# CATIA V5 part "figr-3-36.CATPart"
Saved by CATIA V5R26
Part number: Part1
Bounding box of the stored display mesh (mm): x 0 to 71.72, y -62.404 to 71.526, z 0 to 0
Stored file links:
  D:\_Deepak\CATIA\CATIA V5 2015 Parts Files\Part files\Partfiles\c03_catia_v5_6r2015_prt\figr-3-36.CATPart
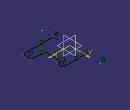
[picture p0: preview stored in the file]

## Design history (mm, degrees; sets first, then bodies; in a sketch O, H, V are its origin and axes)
Body1 (main body)
  Sketch1 on xy-plane, origin (0, 0, 0), H (1, 0, 0), V (0, 1, 0)
    axis line L1 (0, 71.5261) -> (1.8602, -62.4039)
    point P1 (0, 71.5261)
    line L2 (0.4896, 36.2738) -> (51.465, 36.2738)
    point P3 (0.4896, 36.2738)
    line L3 (51.465, 36.2738) -> (51.465, 23.0127)
    line L4 (51.465, 23.0127) -> (41.544, 23.0127)
    line L5 (41.544, 23.0127) -> (41.544, -16.3784)
    line L6 (41.544, -16.3784) -> (71.7203, -16.3784)
    line L7 (71.7203, -16.3784) -> (71.7203, -36.696)
    line L8 (71.7203, -36.696) -> (1.5031, -36.696)
    point P10 (1.5031, -36.696)
    coincidence: P1 V, P3 L1, P10 L1
    horizontal: L2 H, L4 H, L6 H, L8 H
    vertical: L3 V, L5 V, L7 V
